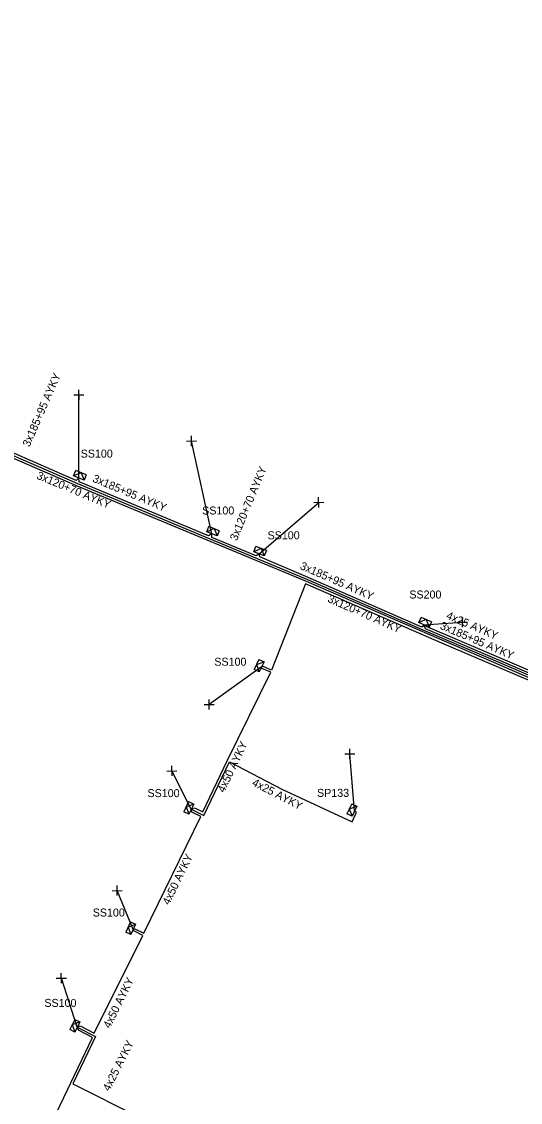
# Model space of a CAD drawing. Extents: x -762500 to -761285, y -1155006 to -1154135.
# Drawn here: x -762085.9 to -762023.9, y -1154863.6 to -1154729.3 of the extents above; entities that cross this region are included whole.
import ezdxf

# ---------------------------------------------------------------- set-up
doc = ezdxf.new("R2010")
doc.units = 0
for name, color, linetype in [('Vrstva 31', 7, 'Continuous'), ('Vrstva 33', 7, 'Continuous'), ('Vrstva 34', 7, 'Continuous'), ('Vrstva 5', 7, 'Continuous'), ('Vrstva 59', 7, 'Continuous'), ('Vrstva 6', 7, 'Continuous')]:
    doc.layers.add(name, color=color, linetype=linetype)

msp = doc.modelspace()

# ---------------------------------------------------------------- linework, layer by layer
at = {"layer": 'Vrstva 31'}
for points in [[(-762077.909, -1154785.6), (-762078.182, -1154786.245), (-762079.471, -1154785.698), (-762079.198, -1154785.053)], [(-762078.553, -1154785.327), (-762079.471, -1154785.698)], [(-762077.909, -1154785.6), (-762079.198, -1154785.053)], [(-762078.553, -1154785.327), (-762078.182, -1154786.245)], [(-762061.366, -1154792.524), (-762061.628, -1154793.173), (-762062.926, -1154792.649), (-762062.664, -1154792)], [(-762061.366, -1154792.524), (-762062.664, -1154792)], [(-762062.015, -1154792.262), (-762062.926, -1154792.649)], [(-762062.015, -1154792.262), (-762061.628, -1154793.173)], [(-762055.506, -1154795.004), (-762055.768, -1154795.653), (-762057.066, -1154795.129), (-762056.804, -1154794.48)], [(-762056.155, -1154794.742), (-762057.066, -1154795.129)], [(-762055.506, -1154795.004), (-762056.804, -1154794.48)], [(-762056.155, -1154794.742), (-762055.768, -1154795.653)], [(-762034.99, -1154803.85), (-762035.263, -1154804.494), (-762036.552, -1154803.947), (-762036.278, -1154803.303)], [(-762034.99, -1154803.85), (-762035.263, -1154804.494), (-762036.552, -1154803.947), (-762036.278, -1154803.303)], [(-762035.634, -1154803.576), (-762036.552, -1154803.947)], [(-762035.634, -1154803.576), (-762036.552, -1154803.947)], [(-762034.99, -1154803.85), (-762036.278, -1154803.303)], [(-762034.99, -1154803.85), (-762036.278, -1154803.303)], [(-762035.634, -1154803.576), (-762035.263, -1154804.494)], [(-762035.634, -1154803.576), (-762035.263, -1154804.494)], [(-762056.431, -1154808.511), (-762057.045, -1154809.769)], [(-762056.431, -1154808.511), (-762055.802, -1154808.818), (-762056.416, -1154810.076), (-762057.045, -1154809.769)], [(-762056.738, -1154809.14), (-762055.802, -1154808.818)], [(-762056.738, -1154809.14), (-762056.416, -1154810.076)], [(-762065.171, -1154826.181), (-762065.785, -1154827.44)], [(-762065.171, -1154826.181), (-762064.542, -1154826.488), (-762065.156, -1154827.747), (-762065.785, -1154827.44)], [(-762065.478, -1154826.811), (-762064.542, -1154826.488)], [(-762065.478, -1154826.811), (-762065.156, -1154827.747)], [(-762044.898, -1154826.447), (-762045.489, -1154827.715)], [(-762044.898, -1154826.447), (-762044.263, -1154826.742), (-762044.855, -1154828.011), (-762045.489, -1154827.715)], [(-762045.194, -1154827.081), (-762044.263, -1154826.742)], [(-762045.194, -1154827.081), (-762044.855, -1154828.011)], [(-762072.398, -1154841.137), (-762072.989, -1154842.406)], [(-762072.398, -1154841.137), (-762071.763, -1154841.433), (-762072.355, -1154842.702), (-762072.989, -1154842.406)], [(-762072.694, -1154841.772), (-762071.763, -1154841.433)], [(-762072.694, -1154841.772), (-762072.355, -1154842.702)], [(-762079.341, -1154853.261), (-762079.955, -1154854.519)], [(-762079.341, -1154853.261), (-762078.712, -1154853.568), (-762079.326, -1154854.826), (-762079.955, -1154854.519)], [(-762079.648, -1154853.89), (-762078.712, -1154853.568)], [(-762079.648, -1154853.89), (-762079.326, -1154854.826)]]:
    msp.add_lwpolyline(points, dxfattribs=at)
at = {"layer": 'Vrstva 34'}
for points in [[(-762079.435, -1154775.641), (-762078.185, -1154775.619)], [(-762078.799, -1154776.255), (-762078.821, -1154775.005)], [(-762065.435, -1154781.391), (-762064.185, -1154781.369)], [(-762064.799, -1154782.005), (-762064.821, -1154780.755)], [(-762049.625, -1154789.011), (-762048.375, -1154788.989)], [(-762048.989, -1154789.625), (-762049.011, -1154788.375)], [(-762031.755, -1154803.891), (-762030.505, -1154803.869)], [(-762031.119, -1154804.505), (-762031.141, -1154803.255)], [(-762062.619, -1154814.755), (-762062.641, -1154813.505)], [(-762063.255, -1154814.141), (-762062.005, -1154814.119)], [(-762045.755, -1154820.261), (-762044.505, -1154820.239)], [(-762045.119, -1154820.875), (-762045.141, -1154819.625)], [(-762067.875, -1154822.391), (-762066.625, -1154822.369)], [(-762067.239, -1154823.005), (-762067.261, -1154821.755)], [(-762074.685, -1154837.261), (-762073.435, -1154837.239)], [(-762074.049, -1154837.875), (-762074.071, -1154836.625)], [(-762081.625, -1154848.141), (-762080.375, -1154848.119)], [(-762080.989, -1154848.755), (-762081.011, -1154847.505)]]:
    msp.add_lwpolyline(points, dxfattribs=at)
at = {"layer": 'Vrstva 5'}
for points in [[(-762005.47, -1154815.51), (-762005.9, -1154815.54), (-762006.91, -1154817.72), (-762027.5, -1154808.79), (-762050.51, -1154798.85), (-762079.21, -1154786.89), (-762094.1, -1154780.44), (-762101.63, -1154777.4), (-762108.5, -1154774.39), (-762121.62, -1154768.73), (-762128.38, -1154765.83), (-762137.12, -1154763.24), (-762132.4, -1154742.15), (-762126.9, -1154716.57), (-762123.43, -1154700.6), (-762123.89, -1154700.17)], [(-762093.99, -1154780.16), (-762079.09, -1154786.61), (-762062.62, -1154793.49), (-762050.39, -1154798.57), (-762036.07, -1154804.84), (-762027.38, -1154808.52), (-762012.7, -1154814.81), (-762007.08, -1154817.32), (-762006.12, -1154815.27), (-762005.4, -1154815.32)], [(-762062.28, -1154792.91), (-762062.72, -1154793.16), (-762078.79, -1154786.45), (-762078.83, -1154785.97), (-762079.16, -1154786.28), (-762092.24, -1154780.56), (-762092.42, -1154780.15)], [(-762056.42, -1154795.39), (-762056.77, -1154795.63), (-762062.27, -1154793.36), (-762062.28, -1154792.91)], [(-762035.91, -1154804.22), (-762036.18, -1154804.5), (-762050.29, -1154798.32), (-762056.33, -1154795.78), (-762056.42, -1154795.39)], [(-762005.59, -1154815.82), (-762005.72, -1154815.85), (-762006.76, -1154818.1), (-762012.94, -1154815.36), (-762033.69, -1154806.48), (-762050.63, -1154799.12), (-762054.86, -1154809.84), (-762055.91, -1154809.39), (-762056.11, -1154809.45)], [(-762035.91, -1154804.22), (-762035.75, -1154804.69), (-762012.6, -1154814.56), (-762007.23, -1154816.91), (-762006.3, -1154814.93), (-762005.33, -1154815.14)], [(-762035.91, -1154804.22), (-762035.47, -1154804.46), (-762012.48, -1154814.28), (-762011.03, -1154810.29), (-762011.22, -1154809.1)], [(-762064.85, -1154827.12), (-762064.46, -1154826.98), (-762063.4, -1154827.46), (-762060.39, -1154821.14), (-762054.97, -1154810.12), (-762056.07, -1154809.64), (-762056.11, -1154809.45)], [(-762064.85, -1154827.12), (-762063.27, -1154827.9), (-762060.11, -1154821.25), (-762053.57, -1154824.63), (-762044.86, -1154828.71), (-762044.3, -1154827.51), (-762044.56, -1154827.38)], [(-762079.02, -1154854.2), (-762078.65, -1154854.05), (-762076.9, -1154854.95), (-762070.87, -1154842.81), (-762071.99, -1154842.26), (-762072.06, -1154842.07), (-762071.86, -1154842), (-762070.74, -1154842.53), (-762063.67, -1154828.05), (-762064.76, -1154827.5), (-762064.85, -1154827.12)], [(-762102.72, -1154930.4), (-762103.42, -1154930.5), (-762103.86, -1154930.73), (-762104.97, -1154930.03), (-762111.33, -1154927.18), (-762104.86, -1154913.86), (-762094.7, -1154892.93), (-762088.02, -1154878.13), (-762089.28, -1154877.5), (-762089.31, -1154877.33), (-762089.14, -1154877.24), (-762087.84, -1154877.87), (-762077.14, -1154855.52), (-762078.88, -1154854.61), (-762079.02, -1154854.2)], [(-762079.02, -1154854.2), (-762076.74, -1154855.39), (-762079.56, -1154861.27), (-762071.33, -1154865.42)]]:
    msp.add_lwpolyline(points, dxfattribs=at)
at = {"layer": 'Vrstva 59'}
for points in [[(-762078.83, -1154785.97), (-762078.81, -1154775.63)], [(-762062.28, -1154792.91), (-762064.81, -1154781.38)], [(-762056.42, -1154795.39), (-762049, -1154789)], [(-762035.91, -1154804.22), (-762031.13, -1154803.88)], [(-762056.11, -1154809.45), (-762062.63, -1154814.13)], [(-762044.56, -1154827.38), (-762045.13, -1154820.25)], [(-762064.85, -1154827.12), (-762067.25, -1154822.38)], [(-762072.06, -1154842.07), (-762074.06, -1154837.25)], [(-762079.02, -1154854.2), (-762081, -1154848.13)]]:
    msp.add_lwpolyline(points, dxfattribs=at)

# ---------------------------------------------------------------- texts
at = {"layer": 'Vrstva 33'}
for s, p in [('SS100', (-762078.6, -1154783.44)), ('SS100', (-762063.49, -1154790.51)), ('SS100', (-762055.36, -1154793.59)), ('SS200', (-762037.73, -1154800.95)), ('SS100', (-762061.98, -1154809.3)), ('SS100', (-762070.29, -1154825.63)), ('SP133', (-762049.21, -1154825.6)), ('SS100', (-762077.1, -1154840.47)), ('SS100', (-762083.11, -1154851.7))]:
    msp.add_text(s, height=0.9943, dxfattribs=at).set_placement(p)
at = {"layer": 'Vrstva 6'}
for s, height, rotation, p in [('3x185+95 AYKY', 0.99429, 66.37614, (-762084.97, -1154782.18)), ('3x120+70 AYKY', 0.99429, 337.37603, (-762084.16, -1154786.03)), ('3x120+70 AYKY', 0.99429, 67.57428, (-762059.18, -1154793.85)), ('3x185+95 AYKY', 0.99429, 337.33077, (-762077.21, -1154786.4)), ('3x185+95 AYKY', 0.99429, 336.35465, (-762051.41, -1154797.25)), ('3x120+70 AYKY', 0.99429, 336.35594, (-762047.98, -1154801.34)), ('4x25 AYKY', 0.9943, 336.86189, (-762033.23, -1154803.42)), ('3x185+95 AYKY', 0.99429, 336.89588, (-762034, -1154804.69)), ('4x50 AYKY', 0.9943, 64.47612, (-762060.75, -1154825.15)), ('4x25 AYKY', 0.9943, 332.71382, (-762057.38, -1154824.14)), ('4x50 AYKY', 0.9943, 63.95121, (-762067.6, -1154839.11)), ('4x50 AYKY', 0.9943, 63.59198, (-762074.97, -1154854.45)), ('4x25 AYKY', 0.9943, 63.23465, (-762075.03, -1154862.25))]:
    msp.add_text(s, height=height, rotation=rotation, dxfattribs=at).set_placement(p)

doc.saveas('drawing.dxf')
